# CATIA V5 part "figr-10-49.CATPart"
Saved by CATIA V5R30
Part number: Part1
Bounding box of the stored display mesh (mm): x -75 to 75, y 0 to 282.665, z -39.154 to 114.529
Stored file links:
  D:\PROJECTS\CATIA V56R 2020\Resources\Parts File\c10_catia_v5_6r2020_prt\figr-10-49.CATPart
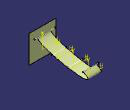
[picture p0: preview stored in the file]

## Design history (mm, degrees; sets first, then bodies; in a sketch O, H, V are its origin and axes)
Body1 (main body)
  Plane1: type Offset, RefPlane zx-plane, Offset 85
  Sketch1 on yz-plane, origin (0, 0, 0), H (0, 1, 0), V (0, 0, 1)
    line L1 (0, 114.5286) -> (0, -39.1536)
    point P1 (0, 114.5286)
    coincidence: P1 V
    vertical: L1 V
  Extrude1: Element1 Sketch1, Lim1 75, Lim2 75
  Plane2: type Offset, RefPlane Plane1, Offset 85
  Plane3: type Offset, RefPlane Plane2, Offset 85
  Sketch2 on zx-plane, origin (0, 0, 0), H (-1, 0, 0), V (0, 0, 1)
    line L1 (-43.9118, 70.4151) -> (71.5537, 70.4151)
    horizontal: L1 H
  Sketch3 on Plane1, origin (0, 85, 0), H (-1, 0, 0), V (0, 0, 1)
    line L1 (-29.1778, 30.4555) -> (46.4999, 30.4555)
    horizontal: L1 H
  Sketch4 on Plane2, origin (0, 170, 0), H (-1, 0, 0), V (0, 0, 1)
    line L1 (-27.284, 11.606) -> (54.5029, 11.606)
    horizontal: L1 H
  Sketch5 on Plane3, origin (0, 255, 0), H (-1, 0, 0), V (0, 0, 1)
    line L1 (-28.2106, 33.1442) -> (56.8447, 33.1442)
    horizontal: L1 H
  Sweep1: type Conic, Guide ({sweepconicextendedguide Guide Sketch2, Reference zx-plane, Angle 0}; Sketch3; Sketch4; Sketch5)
